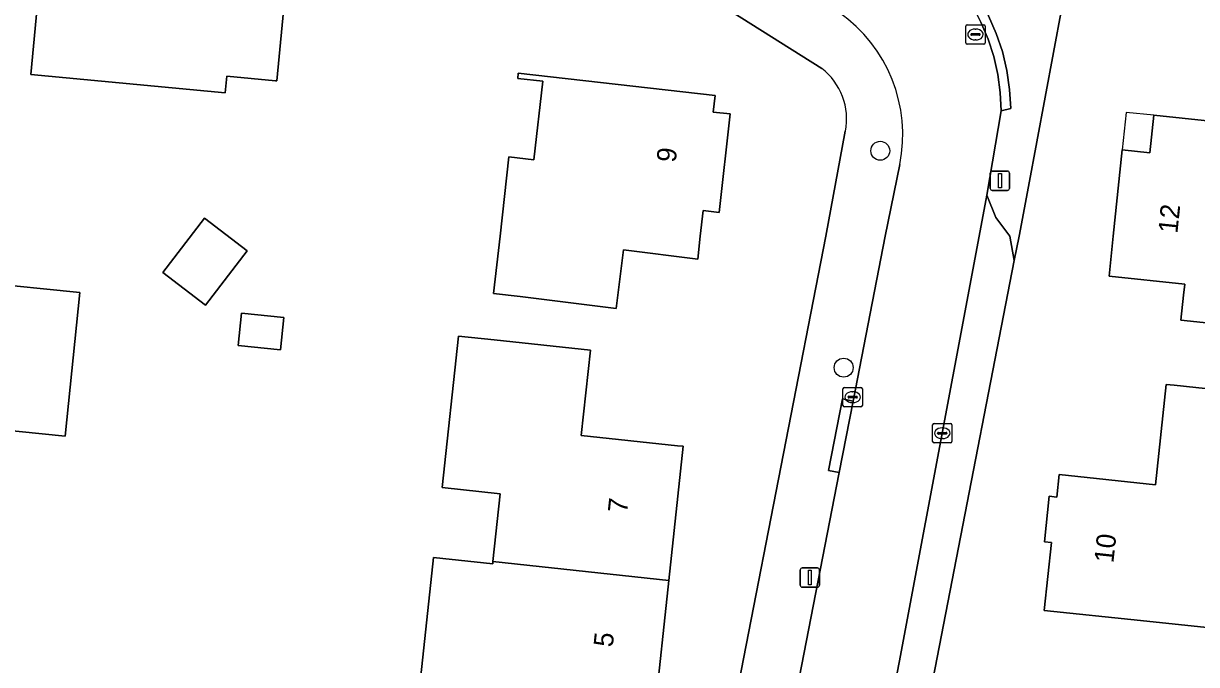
# Model space of a CAD drawing. Extents: x 162396 to 163643, y 386452 to 387406.
# Drawn here: x 162948 to 163008.7, y 386977.8 to 387011 of the extents above; entities that cross this region are included whole.
import ezdxf

# ---------------------------------------------------------------- set-up
doc = ezdxf.new("R2010")
doc.units = 0
for name, color, linetype in [('IMGEO_Boom', 7, 'Continuous'), ('IMGEO_Erf', 7, 'Continuous'), ('IMGEO_Kolk', 7, 'Continuous'), ('IMGEO_Lichtmast', 7, 'Continuous'), ('IMGEO_Pand', 7, 'Continuous'), ('IMGEO_Pand_nummerreeks', 7, 'Continuous'), ('IMGEO_Pand_overbouw', 7, 'Continuous'), ('IMGEO_Parkeervlak_open', 7, 'Continuous'), ('IMGEO_Rijbaan_lokaal_open', 7, 'Continuous'), ('IMGEO_Rioolput', 7, 'Continuous'), ('IMGEO_Voetpad_open', 7, 'Continuous')]:
    doc.layers.add(name, color=color, linetype=linetype)

msp = doc.modelspace()

# ---------------------------------------------------------------- linework, layer by layer
at = {"layer": 'IMGEO_Boom'}
for centre in [(162992.343, 387004.413), (162990.45, 386993.2)]:
    msp.add_circle(centre, 0.489, dxfattribs=at)
at = {"layer": 'IMGEO_Erf'}
for points in [[(162961.225, 387038.18), (162964.459, 387035.953), (162990.052, 387019.93), (162992.795, 387018.215), (163000, 387017.439), (163002.724, 387017.146), (163002.153, 387014.133), (163000, 387002.568), (162999.522, 387000), (162999.273, 386998.733), (162983.452, 386917.174), (162983.338, 386916.58), (162981.778, 386908.453)], [(162989.314, 387008.671), (162953.541, 387031.202), (162934.073, 387000), (162925.999, 386987.383), (162920.22, 386977.995), (162917.756, 386973.029), (162916.265, 386969.23), (162904.686, 386937.076)], [(162989.528, 387000), (162990.536, 387005.429)], [(162972.023, 386910.108), (162989.528, 387000)], [(162945.823, 386997.611), (162950.956, 386997.086), (162950.196, 386989.656), (162944.244, 386990.265)], [(162968.543, 386976.787), (162969.25, 386983.392), (162972.305, 386983.065), (162972.316, 386983.169), (162972.692, 386986.679), (162969.702, 386986.999), (162970.539, 386994.829), (162972.385, 386994.632), (162977.356, 386994.1), (162976.885, 386989.697), (162981.867, 386989.165), (162982.155, 386989.134), (162981.414, 386982.198), (162980.672, 386975.259)]]:
    msp.add_lwpolyline(points, dxfattribs=at)
for points in [[(162948.433, 387008.35), (162949.222, 387016.807), (162953.078, 387016.447), (162954.772, 387016.289), (162955.102, 387019.828), (162962.745, 387019.114), (162962.905, 387019.099), (162962.847, 387018.477), (162967.657, 387018.028), (162967.684, 387018.313), (162968.062, 387018.278), (162967.442, 387011.633), (162962.239, 387012.119), (162962.39, 387013.736), (162962.201, 387013.754), (162961.693, 387013.801), (162961.153, 387008.025), (162961.083, 387008.032), (162958.553, 387008.268), (162958.473, 387007.412)], [(163007.887, 386995.648), (163008.024, 386996.955), (163008.083, 386997.518), (163004.173, 386997.925), (163004.389, 387000), (163004.854, 387004.455), (163006.285, 387004.306), (163006.487, 387006.25), (163009.415, 387005.945), (163009.848, 387010.094), (163019.028, 387009.138), (163018.234, 387001.519), (163014.197, 387001.94), (163013.995, 387000), (163013.753, 386997.684), (163013.48, 386995.065)], [(162972.685, 387000.002), (162973.145, 387004.096), (162974.437, 387003.951), (162974.893, 387008.005), (162973.601, 387008.151), (162973.631, 387008.419), (162983.807, 387007.275), (162983.711, 387006.417), (162984.584, 387006.319), (162984.012, 387001.23), (162983.185, 387001.323), (162983.037, 387000.002), (162982.903, 386998.803), (162979.066, 386999.297), (162978.69, 386996.258), (162973.728, 386996.872), (162972.352, 386997.042)], [(162955.248, 386998.117), (162957.402, 387000.935), (162959.608, 386999.248), (162957.455, 386996.431)], [(162959.146, 386994.338), (162959.319, 386996.02), (162961.504, 386995.797), (162961.332, 386994.114)], [(163012.922, 386986.451), (163012.178, 386979.446), (163005.794, 386980.124), (163000.821, 386980.652), (163001.193, 386984.16), (163000.832, 386984.198), (163001.081, 386986.548), (163001.475, 386986.507), (163001.599, 386987.674), (163006.567, 386987.146), (163007.118, 386992.336), (163007.535, 386992.292), (163013.129, 386991.698), (163014.882, 386991.512), (163014.328, 386986.302)]]:
    msp.add_lwpolyline(points, close=True, dxfattribs=at)
msp.add_arc((162987.326, 387006.07), 3.274, 348.70374, 52.6019, dxfattribs=at)
at = {"layer": 'IMGEO_Kolk'}
for p, q in [((162990.415, 386991.249), (162990.415, 386992.101)), ((162990.49, 386992.175), (162991.342, 386992.175)), ((162990.903, 386991.955), (162990.928, 386991.955)), ((162991.416, 386992.101), (162991.416, 386991.249)), ((162990.674, 386991.669), (162990.674, 386991.681)), ((162991.112, 386991.632), (162990.714, 386991.632)), ((162990.717, 386991.718), (162991.115, 386991.718)), ((162990.926, 386991.395), (162990.901, 386991.395)), ((162991.158, 386991.681), (162991.158, 386991.669)), ((162991.342, 386991.175), (162990.49, 386991.175)), ((162995.046, 386989.383), (162995.046, 386990.235)), ((162995.121, 386990.309), (162995.973, 386990.309)), ((162995.534, 386990.089), (162995.559, 386990.089)), ((162996.047, 386990.235), (162996.047, 386989.383)), ((162995.305, 386989.803), (162995.305, 386989.815)), ((162995.743, 386989.766), (162995.345, 386989.766)), ((162995.348, 386989.852), (162995.746, 386989.852)), ((162995.557, 386989.529), (162995.532, 386989.529)), ((162995.789, 386989.815), (162995.789, 386989.803)), ((162995.973, 386989.309), (162995.121, 386989.309))]:
    msp.add_line(p, q, dxfattribs=at)
for points in [[(162990.415, 386991.249), (162990.415, 386992.101)], [(162990.49, 386992.175), (162991.342, 386992.175)], [(162991.416, 386992.101), (162991.416, 386991.249)], [(162991.342, 386991.175), (162990.49, 386991.175)], [(162995.046, 386989.383), (162995.046, 386990.235)], [(162995.121, 386990.309), (162995.973, 386990.309)], [(162996.047, 386990.235), (162996.047, 386989.383)], [(162995.973, 386989.309), (162995.121, 386989.309)]]:
    msp.add_lwpolyline(points, dxfattribs=at)
for centre, radius, start, end in [((162990.492, 386992.099), 0.0765, 91.55205, 178.44795), ((162990.492, 386992.099), 0.0765, 91.55205, 178.44795), ((162991.34, 386992.099), 0.0765, 1.55205, 88.44795), ((162991.34, 386992.099), 0.0765, 1.55205, 88.44795), ((162990.492, 386991.251), 0.0765, 181.55205, 268.44795), ((162990.492, 386991.251), 0.0765, 181.55205, 268.44795), ((162990.714, 386991.678), 0.0403, 85.87752, 175.75265), ((162990.711, 386991.668), 0.0366, 178.93798, 274.71019), ((162991.115, 386991.675), 0.043, 264.86636, 352.45326), ((162991.119, 386991.68), 0.0386, 1.73085, 96.63898), ((162991.34, 386991.251), 0.0765, 271.55205, 358.44795), ((162991.34, 386991.251), 0.0765, 271.55205, 358.44795), ((162995.123, 386990.233), 0.0765, 91.55205, 178.44795), ((162995.123, 386990.233), 0.0765, 91.55205, 178.44795), ((162995.971, 386990.233), 0.0765, 1.55205, 88.44795), ((162995.971, 386990.233), 0.0765, 1.55205, 88.44795), ((162995.345, 386989.812), 0.0403, 85.87752, 175.75265), ((162995.342, 386989.802), 0.0366, 178.93798, 274.71019), ((162995.746, 386989.809), 0.043, 264.86636, 352.45326), ((162995.75, 386989.814), 0.0386, 1.73085, 96.63898), ((162995.123, 386989.385), 0.0765, 181.55205, 268.44795), ((162995.123, 386989.385), 0.0765, 181.55205, 268.44795), ((162995.971, 386989.385), 0.0765, 271.55205, 358.44795), ((162995.971, 386989.385), 0.0765, 271.55205, 358.44795)]:
    msp.add_arc(centre, radius, start, end, dxfattribs=at)
for centre, major_axis, ratio, start_param, end_param in [((162990.902, 386991.675), (-0.387, 0.002), 0.722429, 4.712389, 7.853982), ((162990.927, 386991.675), (-0.39, 0.002), 0.717154, 1.570796, 4.712389), ((162995.533, 386989.809), (-0.387, 0.002), 0.722429, 4.712389, 7.853982), ((162995.558, 386989.809), (-0.39, 0.002), 0.717154, 1.570796, 4.712389)]:
    msp.add_ellipse(centre, major_axis=major_axis, ratio=ratio, start_param=start_param, end_param=end_param, dxfattribs=at)
at = {"layer": 'IMGEO_Lichtmast'}
for p, q in [((162998.032, 387002.464), (162998.032, 387003.264)), ((162998.032, 387003.264), (162998.032, 387002.464)), ((162998.132, 387003.364), (162998.922, 387003.364)), ((162998.922, 387003.364), (162998.132, 387003.364)), ((162999.022, 387003.264), (162999.022, 387002.464)), ((162999.022, 387002.464), (162999.022, 387003.264)), ((162998.922, 387002.364), (162998.132, 387002.364)), ((162998.132, 387002.364), (162998.922, 387002.364)), ((162988.306, 386982.847), (162989.096, 386982.847)), ((162989.096, 386982.847), (162988.306, 386982.847)), ((162988.206, 386981.947), (162988.206, 386982.747)), ((162988.206, 386982.747), (162988.206, 386981.947)), ((162989.196, 386982.747), (162989.196, 386981.947)), ((162989.196, 386981.947), (162989.196, 386982.747)), ((162989.096, 386981.847), (162988.306, 386981.847)), ((162988.306, 386981.847), (162989.096, 386981.847))]:
    msp.add_line(p, q, dxfattribs=at)
for points in [[(162998.452, 387003.239), (162998.602, 387003.239), (162998.602, 387002.489), (162998.452, 387002.489), (162998.452, 387003.239)], [(162988.626, 386982.722), (162988.776, 386982.722), (162988.776, 386981.972), (162988.626, 386981.972), (162988.626, 386982.722)]]:
    msp.add_lwpolyline(points, dxfattribs=at)
for centre, start, end in [((162998.132, 387003.264), 90, 180), ((162998.132, 387003.264), 90, 180), ((162998.922, 387003.264), 0, 90), ((162998.922, 387003.264), 360, 90), ((162998.132, 387002.464), 180, 270), ((162998.132, 387002.464), 180, 270), ((162998.922, 387002.464), 270, 0), ((162998.922, 387002.464), 270, 0), ((162988.306, 386982.747), 90, 180), ((162988.306, 386982.747), 90, 180), ((162989.096, 386982.747), 0, 90), ((162989.096, 386982.747), 360, 90), ((162988.306, 386981.947), 180, 270), ((162988.306, 386981.947), 180, 270), ((162989.096, 386981.947), 270, 0), ((162989.096, 386981.947), 270, 0)]:
    msp.add_arc(centre, 0.1, start, end, dxfattribs=at)
at = {"layer": 'IMGEO_Pand'}
for points in [[(162961.693, 387013.801), (162962.201, 387013.754), (162962.39, 387013.736), (162962.239, 387012.119), (162967.442, 387011.633), (162968.062, 387018.278), (162967.684, 387018.313), (162967.657, 387018.028), (162962.847, 387018.477), (162962.905, 387019.099), (162962.745, 387019.114), (162955.102, 387019.828), (162954.772, 387016.289), (162953.078, 387016.447), (162949.222, 387016.807), (162948.433, 387008.35), (162958.473, 387007.412), (162958.553, 387008.268), (162961.083, 387008.032), (162961.153, 387008.025)], [(163014.197, 387001.94), (163018.234, 387001.519), (163019.028, 387009.138), (163009.848, 387010.094), (163009.415, 387005.945), (163006.487, 387006.25), (163006.285, 387004.306), (163004.854, 387004.455), (163004.389, 387000), (163004.173, 386997.925), (163008.083, 386997.518), (163008.024, 386996.955), (163007.887, 386995.648), (163013.48, 386995.065), (163013.753, 386997.684), (163013.995, 387000)], [(162983.185, 387001.323), (162984.012, 387001.23), (162984.584, 387006.319), (162983.711, 387006.417), (162983.807, 387007.275), (162973.631, 387008.419), (162973.601, 387008.151), (162974.893, 387008.005), (162974.437, 387003.951), (162973.145, 387004.096), (162972.685, 387000.002), (162972.352, 386997.042), (162973.728, 386996.872), (162978.69, 386996.258), (162979.066, 386999.297), (162982.903, 386998.803), (162983.037, 387000.002)], [(162955.248, 386998.117), (162957.455, 386996.431), (162959.608, 386999.248), (162957.402, 387000.935)], [(162943.867, 386986.581), (162944.244, 386990.265), (162950.196, 386989.656), (162950.956, 386997.086), (162945.823, 386997.611), (162940.848, 386998.12), (162940.82, 386997.847), (162942.831, 386997.641), (162942.448, 386993.898), (162935.544, 386994.604), (162934.818, 386987.507)], [(162959.146, 386994.338), (162961.332, 386994.114), (162961.504, 386995.797), (162959.319, 386996.02)], [(162981.414, 386982.198), (162982.155, 386989.134), (162981.867, 386989.165), (162976.885, 386989.697), (162977.356, 386994.1), (162972.385, 386994.632), (162970.539, 386994.829), (162969.702, 386986.999), (162972.692, 386986.679), (162972.316, 386983.169)], [(163007.535, 386992.292), (163007.118, 386992.336), (163006.567, 386987.146), (163001.599, 386987.674), (163001.475, 386986.507), (163001.081, 386986.548), (163000.832, 386984.198), (163001.193, 386984.16), (163000.821, 386980.652), (163005.794, 386980.124), (163012.178, 386979.446), (163012.922, 386986.451), (163014.328, 386986.302), (163014.882, 386991.512), (163013.129, 386991.698)], [(162981.414, 386982.198), (162972.316, 386983.169), (162972.305, 386983.065), (162969.25, 386983.392), (162968.543, 386976.787), (162965.09, 386977.156), (162964.739, 386973.874), (162964.574, 386972.337), (162971.855, 386971.541), (162974.825, 386971.223), (162975.318, 386975.831), (162980.672, 386975.259)]]:
    msp.add_lwpolyline(points, close=True, dxfattribs=at)
at = {"layer": 'IMGEO_Pand_overbouw'}
msp.add_lwpolyline([(163006.487, 387006.25), (163005.057, 387006.399), (163004.854, 387004.455), (163006.285, 387004.306)], close=True, dxfattribs=at)
at = {"layer": 'IMGEO_Parkeervlak_open'}
msp.add_lwpolyline([(162983.338, 386916.58), (162983.452, 386917.174), (162999.273, 386998.733), (162999.047, 387000), (162998.325, 387000.972), (162997.854, 387002.124), (162997.457, 387000), (162993.323, 386977.949), (162980.793, 386913.448)], dxfattribs=at)
at = {"layer": 'IMGEO_Rijbaan_lokaal_open'}
for points in [[(162980.171, 386910.241), (162980.793, 386913.448), (162993.323, 386977.949), (162997.457, 387000), (162997.854, 387002.124), (162998.585, 387006.471), (162998.543, 387007.419), (162998.417, 387008.359), (162998.207, 387009.284), (162997.916, 387010.187), (162997.545, 387011.06), (162997.313, 387011.515)], [(162993.351, 387003.708), (162992.593, 387000), (162990.936, 386991.471), (162990.218, 386987.772), (162987.431, 386973.419), (162985.908, 386965.577), (162983.057, 386950.899), (162982.357, 386947.293), (162975.116, 386910.354)]]:
    msp.add_lwpolyline(points, dxfattribs=at)
msp.add_arc((162985.811, 387005.251), 7.696, 348.43125, 55.13133, dxfattribs=at)
at = {"layer": 'IMGEO_Rioolput'}
for p, q in [((162996.764, 387010), (162996.764, 387010.852)), ((162996.839, 387010.926), (162997.691, 387010.926)), ((162997.252, 387010.706), (162997.277, 387010.706)), ((162997.765, 387010.852), (162997.765, 387010)), ((162997.023, 387010.42), (162997.023, 387010.432)), ((162997.461, 387010.383), (162997.063, 387010.383)), ((162997.066, 387010.469), (162997.464, 387010.469)), ((162997.275, 387010.146), (162997.25, 387010.146)), ((162997.507, 387010.432), (162997.507, 387010.42)), ((162997.691, 387009.926), (162996.839, 387009.926))]:
    msp.add_line(p, q, dxfattribs=at)
for points in [[(162996.764, 387010), (162996.764, 387010.852)], [(162996.839, 387010.926), (162997.691, 387010.926)], [(162997.765, 387010.852), (162997.765, 387010)], [(162997.691, 387009.926), (162996.839, 387009.926)]]:
    msp.add_lwpolyline(points, dxfattribs=at)
for centre, radius, start, end in [((162996.841, 387010.85), 0.0765, 91.55205, 178.44795), ((162996.841, 387010.85), 0.0765, 91.55205, 178.44795), ((162997.689, 387010.85), 0.0765, 1.55205, 88.44795), ((162997.689, 387010.85), 0.0765, 1.55205, 88.44795), ((162997.063, 387010.429), 0.0403, 85.87752, 175.75265), ((162997.06, 387010.419), 0.0366, 178.93798, 274.71019), ((162997.464, 387010.426), 0.043, 264.86636, 352.45326), ((162997.468, 387010.431), 0.0386, 1.73085, 96.63898), ((162996.841, 387010.002), 0.0765, 181.55205, 268.44795), ((162996.841, 387010.002), 0.0765, 181.55205, 268.44795), ((162997.689, 387010.002), 0.0765, 271.55205, 358.44795), ((162997.689, 387010.002), 0.0765, 271.55205, 358.44795)]:
    msp.add_arc(centre, radius, start, end, dxfattribs=at)
for centre, major_axis, ratio, start_param, end_param in [((162997.251, 387010.426), (-0.387, 0.002), 0.722429, 4.712389, 7.853982), ((162997.276, 387010.426), (-0.39, 0.002), 0.717154, 1.570796, 4.712389)]:
    msp.add_ellipse(centre, major_axis=major_axis, ratio=ratio, start_param=start_param, end_param=end_param, dxfattribs=at)
at = {"layer": 'IMGEO_Voetpad_open'}
for points in [[(162954.737, 387033.221), (162953.541, 387031.202), (162989.314, 387008.671)], [(162997.313, 387011.515), (162997.812, 387011.641), (162997.94, 387011.389), (162998.339, 387010.48), (162998.655, 387009.538), (162998.886, 387008.572), (162999.029, 387007.589), (162999.084, 387006.597), (162998.585, 387006.471), (162997.854, 387002.124), (162998.325, 387000.972), (162999.047, 387000), (162999.273, 386998.733), (162999.522, 387000), (163000, 387002.568), (163002.153, 387014.133), (163002.724, 387017.146), (163000, 387017.439), (162992.795, 387018.215), (162990.052, 387019.93), (162991.074, 387017.691)], [(162990.536, 387005.429), (162989.528, 387000), (162972.023, 386910.108)], [(162982.357, 386947.293), (162981.822, 386947.396), (162982.513, 386951.003), (162983.057, 386950.899), (162985.908, 386965.577), (162985.34, 386965.688), (162986.855, 386973.532), (162987.431, 386973.419), (162990.218, 386987.772), (162989.66, 386987.883), (162990.388, 386991.58), (162990.936, 386991.471), (162992.593, 387000), (162993.351, 387003.708)]]:
    msp.add_lwpolyline(points, dxfattribs=at)
for points in [[(162998.585, 387006.471), (162999.084, 387006.597), (162999.029, 387007.589), (162998.886, 387008.572), (162998.655, 387009.538), (162998.339, 387010.48), (162997.94, 387011.389), (162997.812, 387011.641), (162997.313, 387011.515), (162997.545, 387011.06), (162997.916, 387010.187), (162998.207, 387009.284), (162998.417, 387008.359), (162998.543, 387007.419)], [(162990.936, 386991.471), (162990.388, 386991.58), (162989.66, 386987.883), (162990.218, 386987.772)]]:
    msp.add_lwpolyline(points, close=True, dxfattribs=at)
for centre, radius, start, end in [((162985.811, 387005.251), 7.696, 348.43125, 55.13133), ((162987.326, 387006.07), 3.274, 348.70374, 52.6019)]:
    msp.add_arc(centre, radius, start, end, dxfattribs=at)

# ---------------------------------------------------------------- texts
at = {"layer": 'IMGEO_Pand_nummerreeks'}
for s, rotation, p in [('9', 83.58881, (162981.763, 387003.782)), ('12', 84.04718, (163007.7, 387000.115)), ('7', 83.89383, (162979.248, 386985.66)), ('10', 83.67772, (163004.389, 386983.074)), ('5', 83.90394, (162978.508, 386978.722))]:
    msp.add_text(s, height=1, rotation=rotation, dxfattribs=at).set_placement(p)

doc.saveas('drawing.dxf')
